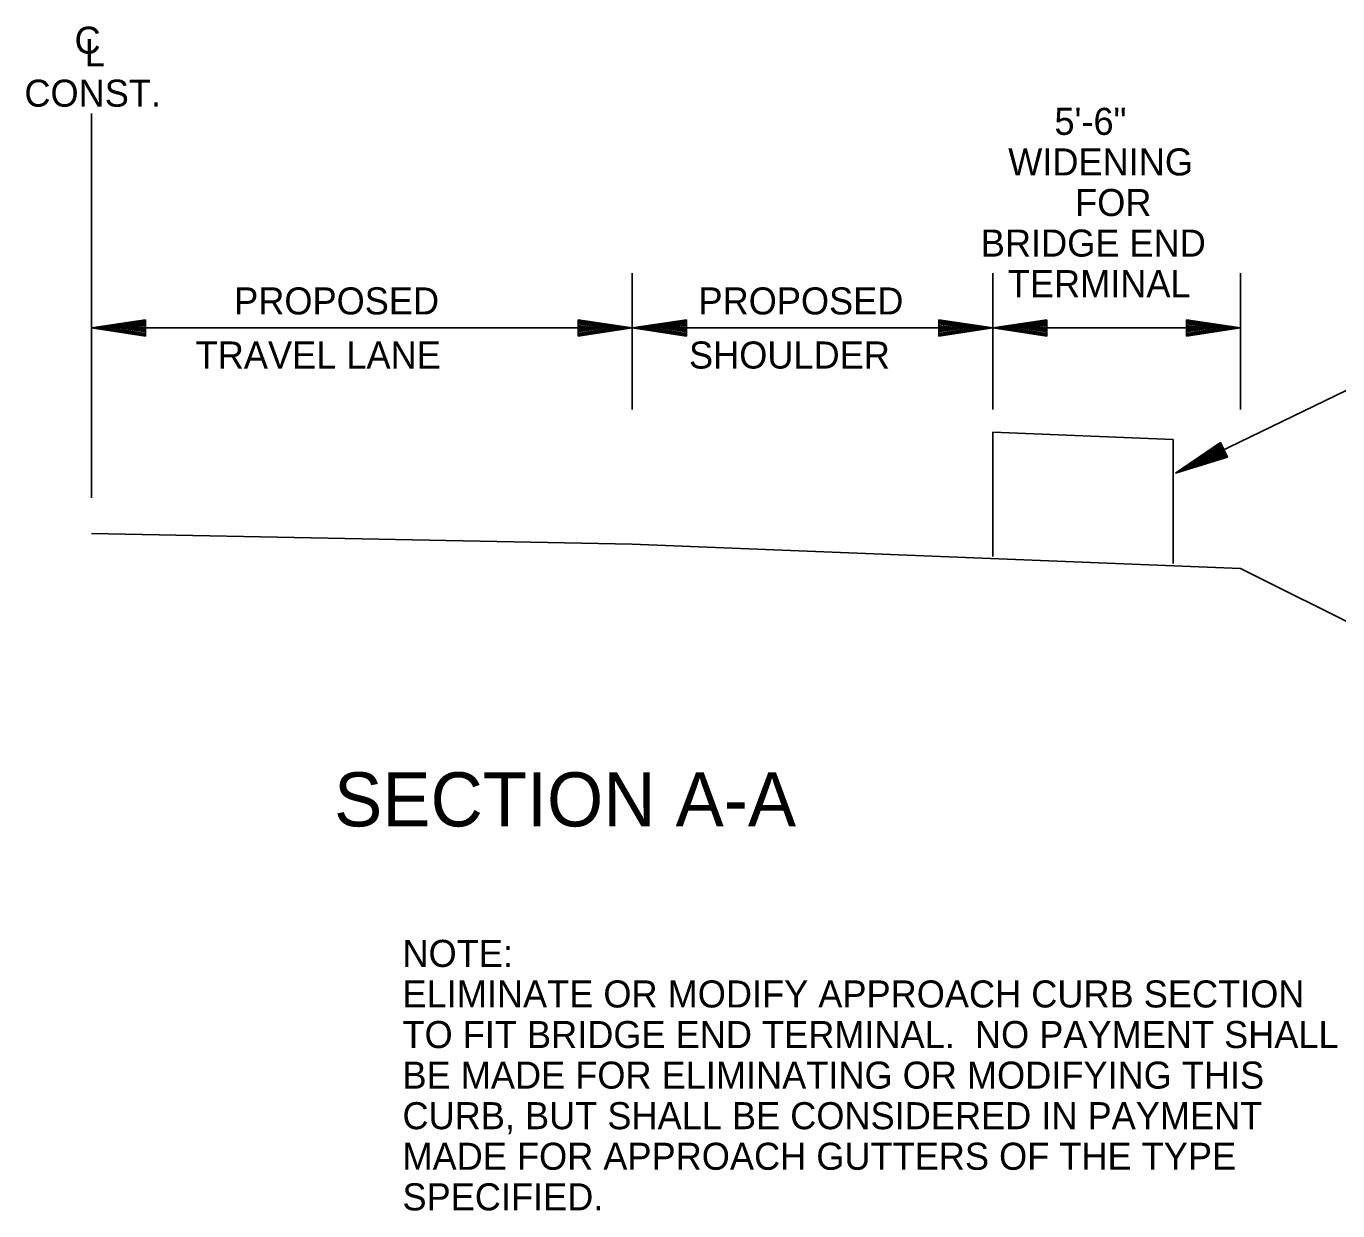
# Model space of a CAD drawing. Extents: x 3314 to 1767681, y -207 to 581440.
# Drawn here: x 3313.9 to 3372.1, y -65.4 to -12.9 of the extents above; entities that cross this region are included whole.
import ezdxf

# ---------------------------------------------------------------- set-up
doc = ezdxf.new("R2010")
doc.units = 0
doc.layers.add('Default', color=7, linetype='Continuous')

msp = doc.modelspace()

# ---------------------------------------------------------------- linework, layer by layer
at = {"layer": 'Default'}
for p, q in [((3316.818, -16.751), (3316.818, -33.811)), ((3340.818, -23.831), (3340.818, -29.891)), ((3356.818, -23.831), (3356.818, -29.891)), ((3367.818, -23.831), (3367.818, -29.891)), ((3319.218, -25.909), (3316.818, -26.269)), ((3319.218, -25.969), (3317.218, -26.269)), ((3319.218, -26.031), (3317.632, -26.269)), ((3319.218, -26.091), (3318.032, -26.269)), ((3319.218, -26.151), (3318.438, -26.269)), ((3319.218, -26.629), (3319.218, -25.909)), ((3338.418, -25.909), (3340.818, -26.269)), ((3338.418, -25.909), (3338.418, -26.629)), ((3338.418, -25.969), (3340.418, -26.269)), ((3338.418, -26.031), (3340.004, -26.269)), ((3338.418, -26.091), (3339.604, -26.269)), ((3338.418, -26.153), (3339.198, -26.269)), ((3343.218, -25.909), (3340.818, -26.269)), ((3343.218, -25.969), (3341.218, -26.269)), ((3343.218, -26.031), (3341.632, -26.269)), ((3343.218, -26.091), (3342.032, -26.269)), ((3343.218, -26.151), (3342.438, -26.269)), ((3343.218, -26.629), (3343.218, -25.909)), ((3354.418, -25.909), (3356.818, -26.269)), ((3354.418, -25.909), (3354.418, -26.629)), ((3354.418, -25.969), (3356.418, -26.269)), ((3354.418, -26.031), (3356.004, -26.269)), ((3354.418, -26.091), (3355.604, -26.269)), ((3354.418, -26.153), (3355.198, -26.269)), ((3359.218, -25.909), (3356.818, -26.269)), ((3359.218, -25.969), (3357.218, -26.269)), ((3359.218, -26.031), (3357.632, -26.269)), ((3359.218, -26.091), (3358.032, -26.269)), ((3359.218, -26.151), (3358.438, -26.269)), ((3359.218, -26.629), (3359.218, -25.909)), ((3365.418, -25.909), (3367.818, -26.269)), ((3365.418, -25.909), (3365.418, -26.629)), ((3365.418, -25.969), (3367.418, -26.269)), ((3365.418, -26.031), (3367.004, -26.269)), ((3365.418, -26.091), (3366.604, -26.269)), ((3365.418, -26.153), (3366.198, -26.269)), ((3316.818, -26.269), (3340.818, -26.269)), ((3319.218, -26.629), (3316.818, -26.269)), ((3319.218, -26.569), (3317.218, -26.269)), ((3319.218, -26.507), (3317.632, -26.269)), ((3319.218, -26.447), (3318.032, -26.269)), ((3319.218, -26.385), (3318.438, -26.269)), ((3319.218, -26.213), (3318.838, -26.269)), ((3319.218, -26.325), (3318.838, -26.269)), ((3338.418, -26.213), (3338.798, -26.269)), ((3338.418, -26.629), (3340.818, -26.269)), ((3338.418, -26.387), (3339.198, -26.269)), ((3338.418, -26.507), (3340.004, -26.269)), ((3338.418, -26.569), (3340.418, -26.269)), ((3338.418, -26.447), (3339.604, -26.269)), ((3338.418, -26.325), (3338.798, -26.269)), ((3340.818, -26.269), (3356.818, -26.269)), ((3343.218, -26.629), (3340.818, -26.269)), ((3343.218, -26.569), (3341.218, -26.269)), ((3343.218, -26.507), (3341.632, -26.269)), ((3343.218, -26.447), (3342.032, -26.269)), ((3343.218, -26.385), (3342.438, -26.269)), ((3343.218, -26.213), (3342.838, -26.269)), ((3343.218, -26.325), (3342.838, -26.269)), ((3354.418, -26.213), (3354.798, -26.269)), ((3354.418, -26.629), (3356.818, -26.269)), ((3354.418, -26.387), (3355.198, -26.269)), ((3354.418, -26.507), (3356.004, -26.269)), ((3354.418, -26.569), (3356.418, -26.269)), ((3354.418, -26.447), (3355.604, -26.269)), ((3354.418, -26.325), (3354.798, -26.269)), ((3356.818, -26.269), (3367.818, -26.269)), ((3359.218, -26.629), (3356.818, -26.269)), ((3359.218, -26.569), (3357.218, -26.269)), ((3359.218, -26.507), (3357.632, -26.269)), ((3359.218, -26.447), (3358.032, -26.269)), ((3359.218, -26.385), (3358.438, -26.269)), ((3359.218, -26.213), (3358.838, -26.269)), ((3359.218, -26.325), (3358.838, -26.269)), ((3365.418, -26.213), (3365.798, -26.269)), ((3365.418, -26.629), (3367.818, -26.269)), ((3365.418, -26.387), (3366.198, -26.269)), ((3365.418, -26.507), (3367.004, -26.269)), ((3365.418, -26.569), (3367.418, -26.269)), ((3365.418, -26.447), (3366.604, -26.269)), ((3365.418, -26.325), (3365.798, -26.269)), ((3364.92, -32.717), (3375.36, -27.655)), ((3356.818, -30.897), (3356.818, -36.401)), ((3356.818, -30.897), (3364.818, -31.217)), ((3364.818, -31.217), (3364.818, -36.721)), ((3366.922, -31.345), (3364.92, -32.717)), ((3366.948, -31.399), (3365.28, -32.543)), ((3367.236, -31.993), (3366.922, -31.345)), ((3367.236, -31.993), (3364.92, -32.717)), ((3367.21, -31.939), (3365.28, -32.543)), ((3366.976, -31.455), (3365.652, -32.363)), ((3367.184, -31.885), (3365.652, -32.363)), ((3367.002, -31.509), (3366.012, -32.187)), ((3367.158, -31.831), (3366.012, -32.187)), ((3367.028, -31.565), (3366.378, -32.011)), ((3367.13, -31.775), (3366.378, -32.011)), ((3367.054, -31.619), (3366.738, -31.835)), ((3367.104, -31.721), (3366.738, -31.835)), ((3316.818, -35.381), (3340.818, -35.861)), ((3340.818, -35.861), (3367.818, -36.941)), ((3367.818, -36.941), (3384.18, -45.121))]:
    msp.add_line(p, q, dxfattribs=at)

# ---------------------------------------------------------------- texts
for s, height, p in [('C', 1.2, (3316.062, -14.102)), ('L', 1.2, (3316.512, -14.657)), ('CONST.', 1.2, (3313.836, -16.453)), ('5\'-6" ', 1.2, (3359.552, -17.703)), ('WIDENING', 1.2, (3357.501, -19.503)), ('FOR', 1.2, (3360.471, -21.303)), ('BRIDGE END', 1.2, (3356.285, -23.103)), ('TERMINAL', 1.2, (3357.482, -24.903)), ('PROPOSED', 1.2, (3323.146, -25.669)), ('PROPOSED', 1.2, (3343.754, -25.669)), ('TRAVEL LANE', 1.2, (3321.438, -28.069)), ('SHOULDER', 1.2, (3343.334, -28.069)), ('SECTION A-A', 2.4, (3327.58, -48.381)), ('NOTE:', 1.2, (3330.616, -54.613)), ('ELIMINATE OR MODIFY APPROACH CURB SECTION', 1.2, (3330.616, -56.413)), ('TO FIT BRIDGE END TERMINAL.  NO PAYMENT SHALL', 1.2, (3330.616, -58.213)), ('BE MADE FOR ELIMINATING OR MODIFYING THIS', 1.2, (3330.616, -60.013)), ('CURB, BUT SHALL BE CONSIDERED IN PAYMENT', 1.2, (3330.616, -61.813)), ('MADE FOR APPROACH GUTTERS OF THE TYPE', 1.2, (3330.616, -63.613)), ('SPECIFIED.', 1.2, (3330.616, -65.413))]:
    msp.add_text(s, height=height, dxfattribs=at).set_placement(p)

doc.saveas('drawing.dxf')
